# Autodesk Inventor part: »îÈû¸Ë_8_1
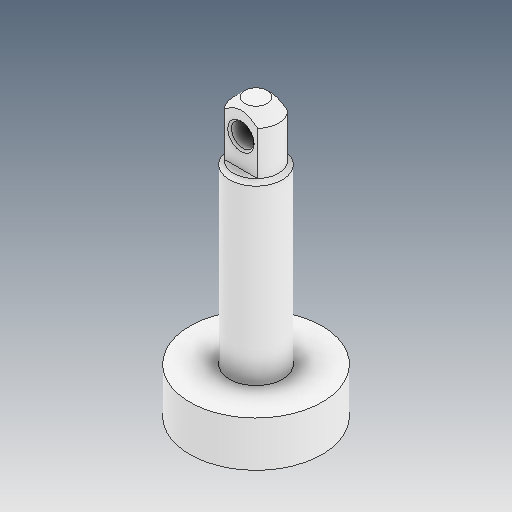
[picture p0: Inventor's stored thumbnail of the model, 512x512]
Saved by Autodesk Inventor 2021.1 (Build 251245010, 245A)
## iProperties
Created: 2021-05
Part Number: »îÈû¸Ë_8_1
Material: Ogólny
Document SubType Name: Modeling
Designer: user
Density: 1 g/cm^3
Appearance: Domyślna
Author: user
Revision Number: ÈÎºÎ
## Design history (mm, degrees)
feature "ÊäÈë1"
node "Bryła1"
